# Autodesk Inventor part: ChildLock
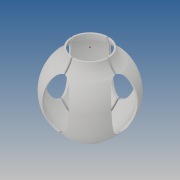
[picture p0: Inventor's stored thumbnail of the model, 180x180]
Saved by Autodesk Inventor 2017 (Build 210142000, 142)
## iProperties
Created: 2018-03
Part Number: ChildLock
Material: Generic
Document SubType Name: Modeling
Designer: Default
Density: 1 g/cm^3
Appearance: Default
Author: Default
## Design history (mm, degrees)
sketch "Sketch1"
  geometry: L1 (33.473, 15.22)-(33.473, 16.54); L2 (-32.848, 0)-(91.734, 0); L3 (-31.75, 0)-(-32.848, 0); L4 (-32.848, 0)-(-32.848, 12.748); L5 (-32.848, 12.748)-(-30.817, 12.748); A1 r 31.75 centre (0, 0) between (23.743, 21.08) and (-31.75, 0); A2 r 33.35 centre (0, 0) between (23.051, 24.101) and (-30.817, 12.748); A3 r 19.05 centre (37.988, 33.727) between (23.743, 21.08) and (33.473, 15.22); A4 r 17.77 centre (37.988, 33.727) between (23.051, 24.101) and (33.473, 16.54); 1 further point
  constraints: 10 end point, 9 point on circle, 4 centre point, 2 coincident, 2 point on line, 2 vertical, 1 collinear, 1 concentric, 1 horizontal, 1 perpendicular, 1 tangent
  dimensions: "d0" = 63.5 diameter of A1; "d1" = 1.6 radial gap between concentric circles of A2 A1; "d20" = 19.05 radius of A3
revolve "Revolution1" sketch "Sketch1" stored, may be unused: angle "d2" = 90 deg
sketch "Sketch2"
  geometry: L1 (68.798, 0.5)-(12.748, 0.5); L2 (12.748, 0.5)-(12.748, -0.5); L3 (12.748, -0.5)-(68.798, -0.5); L4 (68.798, -0.5)-(68.798, 0.5); L5 (68.798, 0.5)-(12.748, -0.5); L6 (12.748, 0.5)-(68.798, -0.5); C1 r 12.748 at (0, 0) reference; 3 further points
  constraints: 12 end point, 4 midpoint, 2 parallel, 1 horizontal, 1 horizontal alignment, 1 perpendicular, 1 tangent
  dimensions: "d3" = 1 distance between parallel lines of L1 L3
extrude "Extrusion1" cut sketch "Sketch2" stored distance "d4" = 25.4; taper "d5" = 0 deg
pattern_circular "Circular Pattern1" dims angle "d7" = 360 deg
fillet "Fillet1" dims "d14" = 12.7
sketch "Sketch7"
  geometry: 2 further points; 1 other entity
  constraints: 2 other
extrude "Extrusion3" cut sketch "Sketch7" stored distance "d15" = 25.4; taper "d16" = 0 deg
pattern_circular "Circular Pattern3" dims angle "d18" = 360 deg
sketch "Sketch8"
  geometry: 1 further point
body "Solid1"
